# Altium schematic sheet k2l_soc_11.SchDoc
size 431 x 279 mm; Date: Not shown in title block; ApprovedBy: Not shown in title block; CheckedBy: Not shown in title block; Author: Not shown in title block; CompanyName: Not shown in title block; Engineer: Not shown in title block; Organization: Not shown in title block; Address1: Not shown in title block; Address2: Not shown in title block; Address3: Not shown in title block; Address4: Not shown in title block; DocumentNumber: 13; Revision: Use project parameter SCH_Rev; SheetNumber: 13; SheetTotal: 16; PageSetup: Record=PageOptions¦CenterHorizontal=True¦CenterVertical=True¦PrintScale=1.00¦XCorrection=1.00¦YCorrection=1.00¦PrintKind=0¦BorderSize=5000000¦LeftOffset=0¦BottomOffset=0¦Orientation=2¦PaperLength=1000¦PaperWidth=1000¦Scale=100¦PaperSource=15¦PrintQuality=600¦MediaType=1¦DitherType=10¦PaperKind=Letter¦PrintScaleMode=1
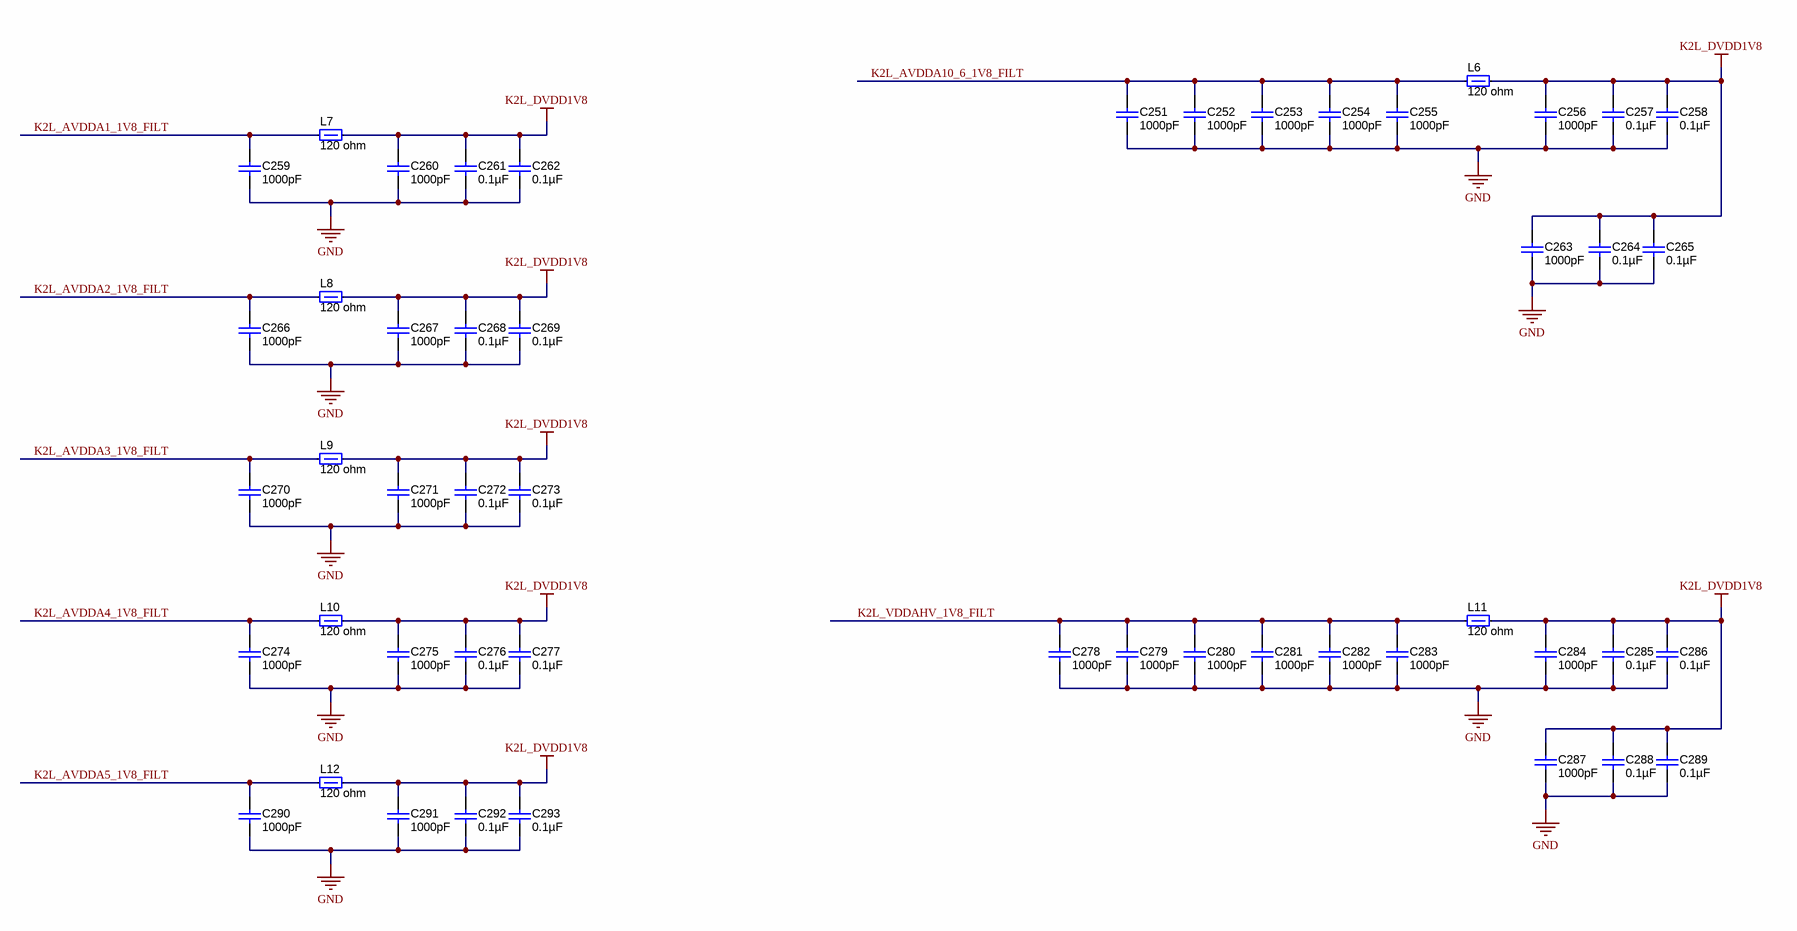
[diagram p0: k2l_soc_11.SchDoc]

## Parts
C251  ValueDisplayed: 1000pF  [0201]  (hidden comment: GRM033R71E102KA01D)
C252  ValueDisplayed: 1000pF  [0201]  (hidden comment: GRM033R71E102KA01D)
C253  ValueDisplayed: 1000pF  [0201]  (hidden comment: GRM033R71E102KA01D)
C254  ValueDisplayed: 1000pF  [0201]  (hidden comment: GRM033R71E102KA01D)
C255  ValueDisplayed: 1000pF  [0201]  (hidden comment: GRM033R71E102KA01D)
C256  ValueDisplayed: 1000pF  [0201]  (hidden comment: GRM033R71E102KA01D)
C257  ValueDisplayed: 0.1µF  [0402]  (hidden comment: GRM152B30J104KE19)
C258  ValueDisplayed: 0.1µF  [0402]  (hidden comment: GRM152B30J104KE19)
C259  ValueDisplayed: 1000pF  [0201]  (hidden comment: GRM033R71E102KA01D)
C260  ValueDisplayed: 1000pF  [0201]  (hidden comment: GRM033R71E102KA01D)
C261  ValueDisplayed: 0.1µF  [0402]  (hidden comment: GRM152B30J104KE19)
C262  ValueDisplayed: 0.1µF  [0402]  (hidden comment: GRM152B30J104KE19)
C263  ValueDisplayed: 1000pF  [0201]  (hidden comment: GRM033R71E102KA01D)
C264  ValueDisplayed: 0.1µF  [0402]  (hidden comment: GRM152B30J104KE19)
C265  ValueDisplayed: 0.1µF  [0402]  (hidden comment: GRM152B30J104KE19)
C266  ValueDisplayed: 1000pF  [0201]  (hidden comment: GRM033R71E102KA01D)
C267  ValueDisplayed: 1000pF  [0201]  (hidden comment: GRM033R71E102KA01D)
C268  ValueDisplayed: 0.1µF  [0402]  (hidden comment: GRM152B30J104KE19)
C269  ValueDisplayed: 0.1µF  [0402]  (hidden comment: GRM152B30J104KE19)
C270  ValueDisplayed: 1000pF  [0201]  (hidden comment: GRM033R71E102KA01D)
C271  ValueDisplayed: 1000pF  [0201]  (hidden comment: GRM033R71E102KA01D)
C272  ValueDisplayed: 0.1µF  [0402]  (hidden comment: GRM152B30J104KE19)
C273  ValueDisplayed: 0.1µF  [0402]  (hidden comment: GRM152B30J104KE19)
C274  ValueDisplayed: 1000pF  [0201]  (hidden comment: GRM033R71E102KA01D)
C275  ValueDisplayed: 1000pF  [0201]  (hidden comment: GRM033R71E102KA01D)
C276  ValueDisplayed: 0.1µF  [0402]  (hidden comment: GRM152B30J104KE19)
C277  ValueDisplayed: 0.1µF  [0402]  (hidden comment: GRM152B30J104KE19)
C278  ValueDisplayed: 1000pF  [0201]  (hidden comment: GRM033R71E102KA01D)
C279  ValueDisplayed: 1000pF  [0201]  (hidden comment: GRM033R71E102KA01D)
C280  ValueDisplayed: 1000pF  [0201]  (hidden comment: GRM033R71E102KA01D)
C281  ValueDisplayed: 1000pF  [0201]  (hidden comment: GRM033R71E102KA01D)
C282  ValueDisplayed: 1000pF  [0201]  (hidden comment: GRM033R71E102KA01D)
C283  ValueDisplayed: 1000pF  [0201]  (hidden comment: GRM033R71E102KA01D)
C284  ValueDisplayed: 1000pF  [0201]  (hidden comment: GRM033R71E102KA01D)
C285  ValueDisplayed: 0.1µF  [0402]  (hidden comment: GRM152B30J104KE19)
C286  ValueDisplayed: 0.1µF  [0402]  (hidden comment: GRM152B30J104KE19)
C287  ValueDisplayed: 1000pF  [0201]  (hidden comment: GRM033R71E102KA01D)
C288  ValueDisplayed: 0.1µF  [0402]  (hidden comment: GRM152B30J104KE19)
C289  ValueDisplayed: 0.1µF  [0402]  (hidden comment: GRM152B30J104KE19)
C290  ValueDisplayed: 1000pF  [0201]  (hidden comment: GRM033R71E102KA01D)
C291  ValueDisplayed: 1000pF  [0201]  (hidden comment: GRM033R71E102KA01D)
C292  ValueDisplayed: 0.1µF  [0402]  (hidden comment: GRM152B30J104KE19)
C293  ValueDisplayed: 0.1µF  [0402]  (hidden comment: GRM152B30J104KE19)
L6  value 120 ohm  [0603]  (hidden comment: BLM18SG121TN1D)
L7  value 120 ohm  [0402]  (hidden comment: BLM15AG121SN1D)
L8  value 120 ohm  [0402]  (hidden comment: BLM15AG121SN1D)
L9  value 120 ohm  [0402]  (hidden comment: BLM15AG121SN1D)
L10  value 120 ohm  [0402]  (hidden comment: BLM15AG121SN1D)
L11  value 120 ohm  [0603]  (hidden comment: BLM18SG121TN1D)
L12  value 120 ohm  [0402]  (hidden comment: BLM15AG121SN1D)

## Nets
GND: C251.2 C252.2 C253.2 C254.2 C255.2 C256.2 C257.2 C258.2 C259.2 C260.2 C261.2 C262.2 C263.2 C264.2 C265.2 C266.2 C267.2 C268.2 C269.2 C270.2 C271.2 C272.2 C273.2 C274.2 C275.2 C276.2 C277.2 C278.2 C279.2 C280.2 C281.2 C282.2 C283.2 C284.2 C285.2 C286.2 C287.2 C288.2 C289.2 C290.2 C291.2 C292.2 C293.2
K2L_DVDD1V8: C256.1 C257.1 C258.1 C260.1 C261.1 C262.1 C263.1 C264.1 C265.1 C267.1 C268.1 C269.1 C271.1 C272.1 C273.1 C275.1 C276.1 C277.1 C284.1 C285.1 C286.1 C287.1 C288.1 C289.1 C291.1 C292.1 C293.1 L6.2 L7.2 L8.2 L9.2 L10.2 L11.2 L12.2
K2L_AVDDA1_1V8_FILT: C259.1 L7.1
K2L_AVDDA2_1V8_FILT: C266.1 L8.1
K2L_AVDDA3_1V8_FILT: C270.1 L9.1
K2L_AVDDA4_1V8_FILT: C274.1 L10.1
K2L_AVDDA5_1V8_FILT: C290.1 L12.1
K2L_AVDDA10_6_1V8_FILT: C251.1 C252.1 C253.1 C254.1 C255.1 L6.1
K2L_VDDAHV_1V8_FILT: C278.1 C279.1 C280.1 C281.1 C282.1 C283.1 L11.1

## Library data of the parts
C251-C256 C259 C260 C263 C266 C267 C270 C271 C274 C275 C278-C284 C287 C290 C291 = GRM033R71E102KA01D: CAP, CERM, 1000 pF, 25 V, +/- 10%, X7R, 0201; Manufacturer: MuRata; Polarized: N; CompType: Capacitor; Value: 1000pF; U/M: EA; Cap_F: 0.000000001; Tolerance_%: 10; Value1: Unknown; VDC_V: 25; Value2: 25V; TaMin_C: -55; TaMax_C: 125
C257 C258 C261 C262 C264 C265 C268 C269 C272 C273 C276 C277 C285 C286 C288 C289 C292 C293 = GRM152B30J104KE19: CAP, CERM, 0.1 µF, 6.3 V, +/- 10%, B, 0402; Manufacturer: MuRata; Polarized: N; CompType: Capacitor; Value: 0.1uF; U/M: EA; Cap_F: 0.0000001; Tolerance_%: 10; Value1: Unknown; VDC_V: 6.3; Value2: 6.3V; TaMin_C: -25; TaMax_C: 85
L6 L11 = BLM18SG121TN1D: Ferrite Bead, 120 ohm @ 100 MHz, 3 A, 0603; Manufacturer: MuRata; Imax_A: 3; DCR_ohm: 0.025; Value1: 0.025 ohm; Value2: 3A; ZTyp@100MHz_Ohm: 120
L7-L10 L12 = BLM15AG121SN1D: Ferrite Bead, 120 ohm @ 100 MHz, 0.55 A, 0402; Manufacturer: MuRata; Imax_A: 0.55; DCR_ohm: 0.19; Value1: 0.19 ohm; Value2: 0.55A; ZTyp@100MHz_Ohm: 120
